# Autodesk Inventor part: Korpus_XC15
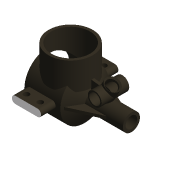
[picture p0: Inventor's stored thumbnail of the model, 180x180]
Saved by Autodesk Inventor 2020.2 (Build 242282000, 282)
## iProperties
Created: 2000-05
Part Number: Korpus_XC15
Document SubType Name: Modeling
Designer: F.Stasiak
Stock Number: Korpus_XC15
Density: 1 g/cm^3
Material: Default
Appearance: Brąz armatni (nowy/polerowany)
Manager: www.cadconsulting.pl
Company: Fabian Stasiak CAD Consulting
Control State: 0
Master: False
Checked Out: False
Shininess: 0.0
Density: 0.0
Volumn: 0.0
Area: 0.0
PropertySet Name: Model Information
Author: F.Stasiak
Subject: Zbiór ćwiczeń. Autodesk Inventor 2020. Kurs podstawowy
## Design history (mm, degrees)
node "Base1"
node "Bryła1"
node "Korpusy bryłowe"
node "Korpusy powierzchniowe"
